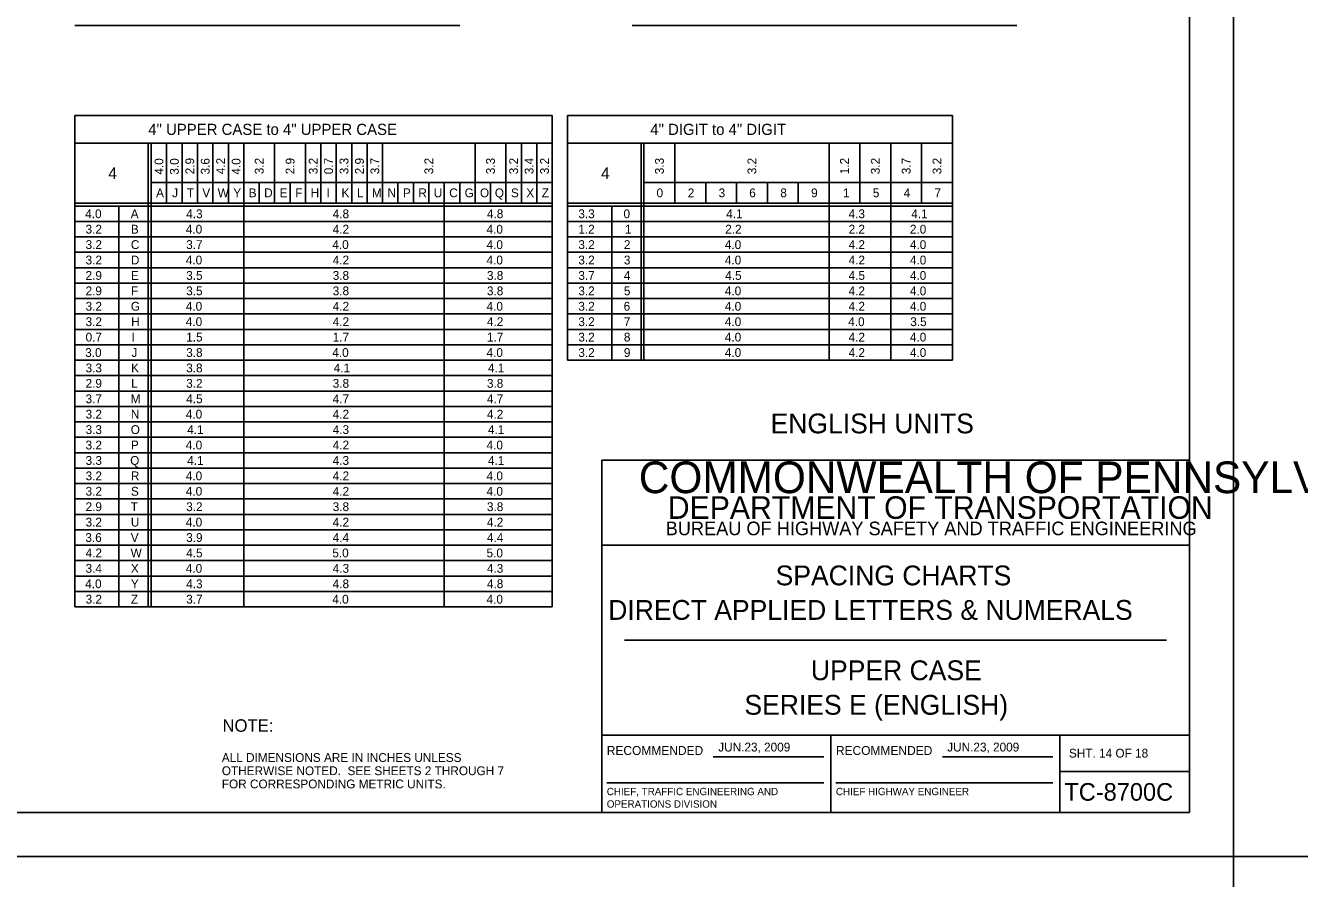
# Model space of a CAD drawing. Extents: x 637580 to 641849, y 297270 to 299646.
# Drawn here: x 640533.1 to 640966.8, y 298450.1 to 298740.6 of the extents above; entities that cross this region are included whole.
import ezdxf

# ---------------------------------------------------------------- set-up
doc = ezdxf.new("R2010")
doc.units = 0
for name, color, linetype in [('1', 7, 'Continuous'), ('2', 7, 'Continuous'), ('XCS-GRID-HVGL', 7, 'Continuous')]:
    doc.layers.add(name, color=color, linetype=linetype)

msp = doc.modelspace()

# ---------------------------------------------------------------- linework, layer by layer
at = {"layer": '1'}
for p, q in [((640929.31, 298472.63), (640929.31, 299036.63)), ((640729.31, 298472.63), (640729.31, 298592.63)), ((640729.31, 298592.63), (640929.31, 298592.63)), ((640929.31, 298563.63), (640729.31, 298563.63)), ((640737.06, 298531.31), (640921.56, 298531.31)), ((640729.31, 298499), (640929.31, 298499)), ((640807.31, 298499), (640807.31, 298472.63)), ((640885.19, 298472.63), (640885.19, 298499)), ((640767.24, 298491.57), (640804.87, 298491.57)), ((640845.24, 298491.57), (640882.87, 298491.57)), ((640885.19, 298486.63), (640929.31, 298486.63)), ((640730.99, 298482.68), (640804.87, 298482.68)), ((640808.99, 298482.68), (640882.87, 298482.68)), ((640929.31, 298472.63), (640143.31, 298472.63)), ((640143.31, 298472.63), (640729.31, 298472.63))]:
    msp.add_line(p, q, dxfattribs=at)
at = {"layer": '2'}
for p, q in [((640549.91, 298740.63), (640680.91, 298740.63)), ((640739.61, 298740.63), (640870.61, 298740.63)), ((640712.41, 298710), (640549.91, 298710)), ((640549.91, 298710), (640549.91, 298542.63)), ((640712.41, 298710), (640712.41, 298542.63)), ((640848.66, 298710), (640717.66, 298710)), ((640717.66, 298710), (640717.66, 298626.63)), ((640848.66, 298626.63), (640848.66, 298710)), ((640549.91, 298700.5), (640712.41, 298700.5)), ((640574.91, 298700.5), (640574.91, 298542.63)), ((640575.91, 298700.5), (640575.91, 298542.63)), ((640581.16, 298700.5), (640581.16, 298680.13)), ((640586.41, 298700.5), (640586.41, 298680.13)), ((640591.66, 298700.5), (640591.66, 298680.13)), ((640596.91, 298700.5), (640596.91, 298680.13)), ((640602.16, 298700.5), (640602.16, 298680.13)), ((640607.41, 298700.5), (640607.41, 298542.63)), ((640617.91, 298700.5), (640617.91, 298680.13)), ((640628.41, 298700.5), (640628.41, 298680.13)), ((640633.66, 298700.5), (640633.66, 298680.13)), ((640638.91, 298700.5), (640638.91, 298680.13)), ((640644.16, 298700.5), (640644.16, 298680.13)), ((640649.41, 298700.5), (640649.41, 298680.13)), ((640654.66, 298700.5), (640654.66, 298680.13)), ((640686.16, 298700.5), (640686.16, 298680.13)), ((640696.66, 298700.5), (640696.66, 298680.13)), ((640701.91, 298700.5), (640701.91, 298680.13)), ((640707.16, 298700.5), (640707.16, 298680.13)), ((640717.66, 298700.5), (640848.66, 298700.5)), ((640742.66, 298700.5), (640742.66, 298626.63)), ((640743.66, 298700.5), (640743.66, 298626.63)), ((640754.16, 298700.5), (640754.16, 298680.13)), ((640806.66, 298700.5), (640806.66, 298626.63)), ((640817.16, 298700.5), (640817.16, 298680.13)), ((640827.66, 298700.5), (640827.66, 298626.63)), ((640838.16, 298700.5), (640838.16, 298680.13)), ((640575.91, 298687.13), (640712.41, 298687.13)), ((640612.66, 298687.13), (640612.66, 298680.13)), ((640623.16, 298687.13), (640623.16, 298680.13)), ((640659.91, 298687.13), (640659.91, 298680.13)), ((640665.16, 298687.13), (640665.16, 298680.13)), ((640670.41, 298687.13), (640670.41, 298680.13)), ((640670.41, 298687.13), (640670.41, 298680.13)), ((640675.66, 298687.13), (640675.66, 298542.63)), ((640680.91, 298687.13), (640680.91, 298680.13)), ((640691.41, 298687.13), (640691.41, 298680.13)), ((640743.66, 298687.13), (640848.66, 298687.13)), ((640764.66, 298687.13), (640764.66, 298680.13)), ((640775.16, 298687.13), (640775.16, 298680.13)), ((640785.66, 298687.13), (640785.66, 298680.13)), ((640796.16, 298687.13), (640796.16, 298680.13)), ((640712.41, 298680.13), (640549.91, 298680.13)), ((640848.66, 298680.13), (640717.66, 298680.13)), ((640712.41, 298679.13), (640549.91, 298679.13)), ((640564.91, 298679.13), (640564.91, 298542.63)), ((640848.66, 298679.13), (640717.66, 298679.13)), ((640732.66, 298679.13), (640732.66, 298626.63)), ((640712.41, 298673.88), (640549.91, 298673.88)), ((640848.66, 298673.88), (640717.66, 298673.88)), ((640712.41, 298668.63), (640549.91, 298668.63)), ((640848.66, 298668.63), (640717.66, 298668.63)), ((640712.41, 298663.38), (640549.91, 298663.38)), ((640848.66, 298663.38), (640717.66, 298663.38)), ((640712.41, 298658.13), (640549.91, 298658.13)), ((640848.66, 298658.13), (640717.66, 298658.13)), ((640712.41, 298652.88), (640549.91, 298652.88)), ((640848.66, 298652.88), (640717.66, 298652.88)), ((640712.41, 298647.63), (640549.91, 298647.63)), ((640848.66, 298647.63), (640717.66, 298647.63)), ((640712.41, 298642.38), (640549.91, 298642.38)), ((640848.66, 298642.38), (640717.66, 298642.38)), ((640712.41, 298637.13), (640549.91, 298637.13)), ((640848.66, 298637.13), (640717.66, 298637.13)), ((640712.41, 298631.88), (640549.91, 298631.88)), ((640848.66, 298631.88), (640717.66, 298631.88)), ((640712.41, 298626.63), (640549.91, 298626.63)), ((640717.66, 298626.63), (640848.66, 298626.63)), ((640712.41, 298621.38), (640549.91, 298621.38)), ((640712.41, 298616.13), (640549.91, 298616.13)), ((640712.41, 298610.88), (640549.91, 298610.88)), ((640712.41, 298605.63), (640549.91, 298605.63)), ((640712.41, 298600.38), (640549.91, 298600.38)), ((640712.41, 298595.13), (640549.91, 298595.13)), ((640712.41, 298589.88), (640549.91, 298589.88)), ((640712.41, 298584.63), (640549.91, 298584.63)), ((640712.41, 298579.38), (640549.91, 298579.38)), ((640712.41, 298574.13), (640549.91, 298574.13)), ((640712.41, 298568.88), (640549.91, 298568.88)), ((640712.41, 298563.63), (640549.91, 298563.63)), ((640712.41, 298558.38), (640549.91, 298558.38)), ((640712.41, 298553.13), (640549.91, 298553.13)), ((640712.41, 298547.88), (640549.91, 298547.88)), ((640549.91, 298542.63), (640549.91, 298542.63)), ((640549.91, 298542.63), (640712.41, 298542.63))]:
    msp.add_line(p, q, dxfattribs=at)
at = {"layer": 'XCS-GRID-HVGL'}
for points in [[(640103.31, 299051.63), (640944.31, 299051.63), (640944.31, 298457.63), (640103.31, 298457.63)], [(640944.31, 299051.63), (641785.31, 299051.63), (641785.31, 298457.63), (640944.31, 298457.63)], [(640103.31, 298457.63), (640944.31, 298457.63), (640944.31, 297863.63), (640103.31, 297863.63)]]:
    msp.add_lwpolyline(points, close=True, dxfattribs=at)

# ---------------------------------------------------------------- texts
at = {"layer": '1'}
for s, height, p in [('COMMONWEALTH OF PENNSYLVANIA', 10.7828, (640741.9, 298581.36)), ('DEPARTMENT OF TRANSPORTATION', 7.6837, (640751.76, 298572.61)), ('BUREAU OF HIGHWAY SAFETY AND TRAFFIC ENGINEERING', 4.6253, (640751.04, 298567.04)), ('SPACING CHARTS', 6.75, (640788.47, 298549.97)), ('DIRECT APPLIED LETTERS & NUMERALS', 6.75, (640731.47, 298538.22)), ('UPPER CASE', 6.75, (640800.47, 298517.66)), ('SERIES E (ENGLISH)', 6.75, (640777.84, 298505.91)), ('RECOMMENDED', 3.048, (640730.99, 298492.2)), ('RECOMMENDED', 3.048, (640808.99, 298492.2)), ('SHT. 14 OF 18', 3, (640888.32, 298491.31)), ('CHIEF, TRAFFIC ENGINEERING AND', 2.5, (640730.99, 298478.51)), ('CHIEF HIGHWAY ENGINEER', 2.5, (640808.99, 298478.51)), ('TC-8700C', 6, (640886.77, 298476.63)), ('OPERATIONS DIVISION', 2.5, (640730.99, 298474.26))]:
    msp.add_text(s, height=height, dxfattribs=at).set_placement(p)
at = {"layer": '2'}
for s, height, p in [('4" UPPER CASE to 4" UPPER CASE', 3.8, (640574.9, 298703.35)), ('4" DIGIT to 4" DIGIT', 3.8, (640745.81, 298703.35)), ('4', 4, (640561.28, 298688.31)), ('4', 4, (640729.03, 298688.31)), ('A', 3, (640577.56, 298682.13)), ('J', 3, (640583.04, 298682.13)), ('T', 3, (640588.04, 298682.13)), ('V', 3, (640593.31, 298682.13)), ('W', 3, (640598.53, 298682.13)), ('Y', 3, (640603.84, 298682.13)), ('B', 3, (640609.1, 298682.13)), ('D', 3, (640614.35, 298682.13)), ('E', 3, (640619.62, 298682.13)), ('F', 3, (640624.92, 298682.13)), ('H', 3, (640630.19, 298682.13)), ('I', 3, (640635.6, 298682.13)), ('K', 3, (640640.69, 298682.13)), ('L', 3, (640645.94, 298682.13)), ('M', 3, (640651.03, 298682.13)), ('N', 3, (640656.35, 298682.13)), ('P', 3, (640661.6, 298682.13)), ('R', 3, (640666.85, 298682.13)), ('U', 3, (640672.09, 298682.13)), ('C', 3, (640677.35, 298682.13)), ('G', 3, (640682.6, 298682.13)), ('O', 3, (640687.81, 298682.13)), ('Q', 3, (640692.88, 298682.13)), ('S', 3, (640698.37, 298682.13)), ('X', 3, (640703.59, 298682.13)), ('Z', 3, (640708.85, 298682.13)), ('0', 3, (640747.93, 298682.13)), ('2', 3, (640758.56, 298682.13)), ('3', 3, (640769.06, 298682.13)), ('6', 3, (640779.48, 298682.13)), ('8', 3, (640790.06, 298682.13)), ('9', 3, (640800.55, 298682.13)), ('1', 3, (640811.4, 298682.13)), ('5', 3, (640821.56, 298682.13)), ('4', 3, (640832.06, 298682.13)), ('7', 3, (640842.56, 298682.13)), ('4.0', 3, (640553.43, 298675)), ('A', 3, (640568.93, 298675)), ('4.3', 3, (640587.81, 298675)), ('4.8', 3, (640637.69, 298675)), ('4.8', 3, (640690.19, 298675)), ('3.3', 3, (640721.31, 298675)), ('0', 3, (640736.68, 298675)), ('4.1', 3, (640771.65, 298675)), ('4.3', 3, (640813.31, 298675)), ('4.1', 3, (640834.65, 298675)), ('3.2', 3, (640553.56, 298669.75)), ('B', 3, (640568.98, 298669.75)), ('4.0', 3, (640587.68, 298669.75)), ('4.2', 3, (640637.69, 298669.75)), ('4.0', 3, (640690.06, 298669.75)), ('1.2', 3, (640721.31, 298669.75)), ('1', 3, (640737.15, 298669.75)), ('2.2', 3, (640771.31, 298669.75)), ('2.2', 3, (640813.31, 298669.75)), ('2.0', 3, (640834.18, 298669.75)), ('3.2', 3, (640553.56, 298664.5)), ('C', 3, (640568.98, 298664.5)), ('3.7', 3, (640587.81, 298664.5)), ('4.0', 3, (640637.56, 298664.5)), ('4.0', 3, (640690.06, 298664.5)), ('3.2', 3, (640721.31, 298664.5)), ('2', 3, (640736.81, 298664.5)), ('4.0', 3, (640771.18, 298664.5)), ('4.2', 3, (640813.31, 298664.5)), ('4.0', 3, (640834.18, 298664.5)), ('3.2', 3, (640553.56, 298659.25)), ('D', 3, (640568.98, 298659.25)), ('4.0', 3, (640587.68, 298659.25)), ('4.2', 3, (640637.69, 298659.25)), ('4.0', 3, (640690.06, 298659.25)), ('3.2', 3, (640721.31, 298659.25)), ('3', 3, (640736.81, 298659.25)), ('4.0', 3, (640771.18, 298659.25)), ('4.2', 3, (640813.31, 298659.25)), ('4.0', 3, (640834.18, 298659.25)), ('2.9', 3, (640553.55, 298654)), ('E', 3, (640568.99, 298654)), ('3.5', 3, (640587.81, 298654)), ('3.8', 3, (640637.69, 298654)), ('3.8', 3, (640690.19, 298654)), ('3.7', 3, (640721.31, 298654)), ('4', 3, (640736.81, 298654)), ('4.5', 3, (640771.31, 298654)), ('4.5', 3, (640813.31, 298654)), ('4.0', 3, (640834.18, 298654)), ('2.9', 3, (640553.55, 298648.75)), ('F', 3, (640569.05, 298648.75)), ('3.5', 3, (640587.81, 298648.75)), ('3.8', 3, (640637.69, 298648.75)), ('3.8', 3, (640690.19, 298648.75)), ('3.2', 3, (640721.31, 298648.75)), ('5', 3, (640736.81, 298648.75)), ('4.0', 3, (640771.18, 298648.75)), ('4.2', 3, (640813.31, 298648.75)), ('4.0', 3, (640834.18, 298648.75)), ('3.2', 3, (640553.56, 298643.5)), ('G', 3, (640568.98, 298643.5)), ('4.0', 3, (640587.68, 298643.5)), ('4.2', 3, (640637.69, 298643.5)), ('4.0', 3, (640690.06, 298643.5)), ('3.2', 3, (640721.31, 298643.5)), ('6', 3, (640736.73, 298643.5)), ('4.0', 3, (640771.18, 298643.5)), ('4.2', 3, (640813.31, 298643.5)), ('4.0', 3, (640834.18, 298643.5)), ('3.2', 3, (640553.56, 298638.25)), ('H', 3, (640569.06, 298638.25)), ('4.0', 3, (640587.68, 298638.25)), ('4.2', 3, (640637.69, 298638.25)), ('4.2', 3, (640690.19, 298638.25)), ('3.2', 3, (640721.31, 298638.25)), ('7', 3, (640736.81, 298638.25)), ('4.0', 3, (640771.18, 298638.25)), ('4.0', 3, (640813.18, 298638.25)), ('3.5', 3, (640834.31, 298638.25)), ('0.7', 3, (640553.56, 298633)), ('I', 3, (640569.23, 298633)), ('1.5', 3, (640587.81, 298633)), ('1.7', 3, (640637.69, 298633)), ('1.7', 3, (640690.19, 298633)), ('3.2', 3, (640721.31, 298633)), ('8', 3, (640736.81, 298633)), ('4.0', 3, (640771.18, 298633)), ('4.2', 3, (640813.31, 298633)), ('4.0', 3, (640834.18, 298633)), ('3.0', 3, (640553.43, 298627.75)), ('J', 3, (640569.17, 298627.75)), ('3.8', 3, (640587.81, 298627.75)), ('4.0', 3, (640637.56, 298627.75)), ('4.0', 3, (640690.06, 298627.75)), ('3.2', 3, (640721.31, 298627.75)), ('9', 3, (640736.8, 298627.75)), ('4.0', 3, (640771.18, 298627.75)), ('4.2', 3, (640813.31, 298627.75)), ('4.0', 3, (640834.18, 298627.75)), ('3.3', 3, (640553.56, 298622.5)), ('K', 3, (640569.06, 298622.5)), ('3.8', 3, (640587.81, 298622.5)), ('4.1', 3, (640638.03, 298622.5)), ('4.1', 3, (640690.53, 298622.5)), ('2.9', 3, (640553.55, 298617.25)), ('L', 3, (640569.06, 298617.25)), ('3.2', 3, (640587.81, 298617.25)), ('3.8', 3, (640637.69, 298617.25)), ('3.8', 3, (640690.19, 298617.25)), ('3.7', 3, (640553.56, 298612)), ('M', 3, (640568.91, 298612)), ('4.5', 3, (640587.81, 298612)), ('4.7', 3, (640637.69, 298612)), ('4.7', 3, (640690.19, 298612)), ('3.2', 3, (640553.56, 298606.75)), ('N', 3, (640568.98, 298606.75)), ('4.0', 3, (640587.68, 298606.75)), ('4.2', 3, (640637.69, 298606.75)), ('4.2', 3, (640690.19, 298606.75)), ('ENGLISH UNITS', 6.75, (640786.74, 298601.72)), ('3.3', 3, (640553.56, 298601.5)), ('O', 3, (640568.93, 298601.5)), ('4.1', 3, (640588.15, 298601.5)), ('4.3', 3, (640637.69, 298601.5)), ('4.1', 3, (640690.53, 298601.5)), ('3.2', 3, (640553.56, 298596.25)), ('P', 3, (640568.98, 298596.25)), ('4.0', 3, (640587.68, 298596.25)), ('4.2', 3, (640637.69, 298596.25)), ('4.0', 3, (640690.06, 298596.25)), ('3.3', 3, (640553.56, 298591)), ('Q', 3, (640568.75, 298591)), ('4.1', 3, (640588.15, 298591)), ('4.3', 3, (640637.69, 298591)), ('4.1', 3, (640690.53, 298591)), ('3.2', 3, (640553.56, 298585.75)), ('R', 3, (640568.98, 298585.75)), ('4.0', 3, (640587.68, 298585.75)), ('4.2', 3, (640637.69, 298585.75)), ('4.0', 3, (640690.06, 298585.75)), ('3.2', 3, (640553.56, 298580.5)), ('S', 3, (640568.99, 298580.5)), ('4.0', 3, (640587.68, 298580.5)), ('4.2', 3, (640637.69, 298580.5)), ('4.0', 3, (640690.06, 298580.5)), ('2.9', 3, (640553.55, 298575.25)), ('T', 3, (640568.92, 298575.25)), ('3.2', 3, (640587.81, 298575.25)), ('3.8', 3, (640637.69, 298575.25)), ('3.8', 3, (640690.19, 298575.25)), ('3.2', 3, (640553.56, 298570)), ('U', 3, (640568.97, 298570)), ('4.0', 3, (640587.68, 298570)), ('4.2', 3, (640637.69, 298570)), ('4.2', 3, (640690.19, 298570)), ('3.6', 3, (640553.48, 298564.75)), ('V', 3, (640568.93, 298564.75)), ('3.9', 3, (640587.8, 298564.75)), ('4.4', 3, (640637.69, 298564.75)), ('4.4', 3, (640690.19, 298564.75)), ('4.2', 3, (640553.56, 298559.5)), ('W', 3, (640568.91, 298559.5)), ('4.5', 3, (640587.81, 298559.5)), ('5.0', 3, (640637.56, 298559.5)), ('5.0', 3, (640690.06, 298559.5)), ('3.4', 3, (640553.56, 298554.25)), ('X', 3, (640568.97, 298554.25)), ('4.0', 3, (640587.68, 298554.25)), ('4.3', 3, (640637.69, 298554.25)), ('4.3', 3, (640690.19, 298554.25)), ('4.0', 3, (640553.43, 298549)), ('Y', 3, (640568.97, 298549)), ('4.3', 3, (640587.81, 298549)), ('4.8', 3, (640637.69, 298549)), ('4.8', 3, (640690.19, 298549)), ('3.2', 3, (640553.56, 298543.75)), ('Z', 3, (640568.98, 298543.75)), ('3.7', 3, (640587.81, 298543.75)), ('4.0', 3, (640637.56, 298543.75)), ('4.0', 3, (640690.06, 298543.75)), ('NOTE:', 4.25, (640600.16, 298500.1)), ('JUN.23, 2009', 3, (640768.93, 298493.39)), ('ALL DIMENSIONS ARE IN INCHES UNLESS', 3, (640599.94, 298489.83)), ('OTHERWISE NOTED.  SEE SHEETS 2 THROUGH 7', 3, (640599.94, 298485.33)), ('FOR CORRESPONDING METRIC UNITS.', 3, (640599.94, 298480.83))]:
    msp.add_text(s, height=height, dxfattribs=at).set_placement(p)
for s, rotation, p in [('4.0', 90, (640580.04, 298689.83)), ('3.0', 90, (640585.29, 298689.83)), ('2.9', 90, (640590.54, 298689.95)), ('3.6', 90, (640595.79, 298689.88)), ('4.2', 90, (640601.04, 298689.96)), ('4.0', 90, (640606.29, 298689.83)), ('3.2', 90, (640614.16, 298689.96)), ('2.9', 90, (640624.66, 298689.95)), ('3.2', 90, (640632.54, 298689.96)), ('0.7', 90, (640637.79, 298689.96)), ('3.3', 90, (640643.04, 298689.96)), ('2.9', 90, (640648.29, 298689.95)), ('3.7', 90, (640653.54, 298689.96)), ('3.2', 90, (640671.91, 298689.96)), ('3.3', 90, (640692.91, 298689.96)), ('3.2', 90, (640700.79, 298689.96)), ('3.4', 90, (640706.04, 298689.96)), ('3.2', 90, (640711.29, 298689.96)), ('3.3', 90, (640750.41, 298689.96)), ('3.2', 90, (640781.91, 298689.96)), ('1.2', 90, (640813.41, 298689.96)), ('3.2', 90, (640823.91, 298689.96)), ('3.7', 90, (640834.41, 298689.96)), ('3.2', 90, (640844.91, 298689.96)), ('JUN.23, 2009', 360, (640846.88, 298493.39))]:
    msp.add_text(s, height=3, rotation=rotation, dxfattribs=at).set_placement(p)

doc.saveas('drawing.dxf')
